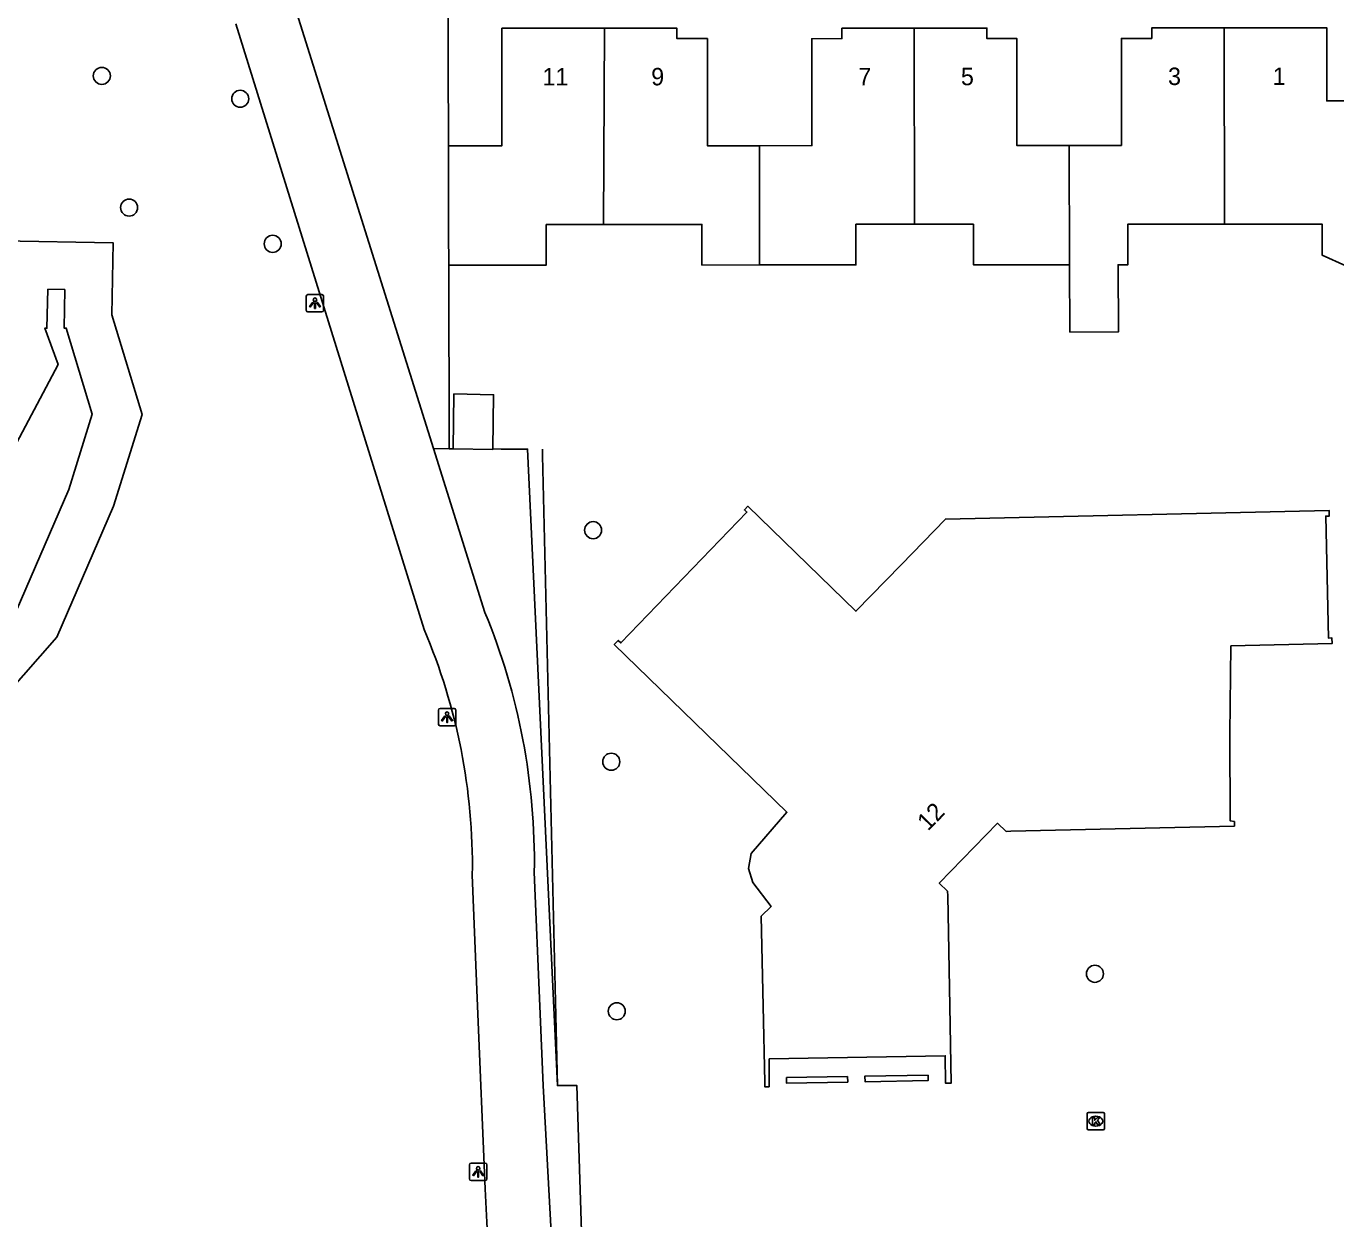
# Model space of a CAD drawing. Extents: x 162880 to 165536, y 384011 to 385179.
# Drawn here: x 163777.7 to 163852.9, y 384237.8 to 384306.2 of the extents above; entities that cross this region are included whole.
import ezdxf

# ---------------------------------------------------------------- set-up
doc = ezdxf.new("R2010")
doc.units = 0
for name, color, linetype in [('IMGEO_Boom', 7, 'Continuous'), ('IMGEO_Fietspad_gesloten', 7, 'Continuous'), ('IMGEO_Groenvoorziening', 7, 'Continuous'), ('IMGEO_Hek', 7, 'Continuous'), ('IMGEO_Kolk', 7, 'Continuous'), ('IMGEO_Lichtpunt', 7, 'Continuous'), ('IMGEO_Pand', 7, 'Continuous'), ('IMGEO_Pand_nummerreeks', 7, 'Continuous'), ('IMGEO_Waterloop', 7, 'Continuous')]:
    doc.layers.add(name, color=color, linetype=linetype)

msp = doc.modelspace()

# ---------------------------------------------------------------- linework, layer by layer
at = {"layer": 'IMGEO_Boom'}
for centre in [(163782.007, 384303.395), (163789.955, 384302.084), (163783.573, 384295.835), (163791.819, 384293.755), (163810.224, 384277.319), (163811.267, 384264.029), (163839.044, 384251.853), (163811.581, 384249.703)]:
    msp.add_circle(centre, 0.489, dxfattribs=at)
at = {"layer": 'IMGEO_Fietspad_gesloten'}
for points in [[(163801.06, 384281.998), (163793.12, 384307.302)], [(163800.515, 384271.617), (163789.704, 384306.385)], [(163801.06, 384281.998), (163804.009, 384272.6)], [(163806.844, 384257.687), (163807.168, 384250), (163807.361, 384245.433), (163808.024, 384233.147)], [(163804.782, 384228.061), (163804.293, 384234.123), (163804.207, 384235.863), (163804.118, 384237.602), (163804.016, 384239.502), (163803.591, 384250), (163803.285, 384257.538)]]:
    msp.add_lwpolyline(points, dxfattribs=at)
for centre, radius, start, end in [((163769.252, 384258.267), 37.597, 359.11675, 22.41053), ((163768.654, 384258.036), 34.635, 359.17548, 23.08573)]:
    msp.add_arc(centre, radius, start, end, dxfattribs=at)
at = {"layer": 'IMGEO_Groenvoorziening'}
for points in [[(163801.871, 384309.184), (163801.92, 384299.385)], [(163776.251, 384293.93), (163782.655, 384293.817), (163782.589, 384289.681), (163784.323, 384283.96), (163782.678, 384278.692), (163779.428, 384271.181), (163766.567, 384256.548)], [(163801.928, 384292.53), (163801.952, 384281.993)], [(163801.952, 384281.993), (163801.06, 384281.998)], [(163801.952, 384281.993), (163802.189, 384281.992)], [(163804.472, 384281.979), (163804.938, 384281.977), (163806.456, 384281.969), (163808.174, 384245.433), (163809.28, 384245.451), (163809.661, 384233.466)]]:
    msp.add_lwpolyline(points, dxfattribs=at)
at = {"layer": 'IMGEO_Hek'}
for points in [[(163807.321, 384281.603), (163807.307, 384281.965)], [(163809.28, 384245.451), (163808.174, 384245.433), (163807.321, 384281.603)]]:
    msp.add_lwpolyline(points, dxfattribs=at)
at = {"layer": 'IMGEO_Kolk'}
for p, q in [((163838.59, 384242.969), (163838.59, 384243.821)), ((163838.665, 384243.895), (163839.517, 384243.895)), ((163839.078, 384243.675), (163839.103, 384243.675)), ((163839.591, 384243.821), (163839.591, 384242.969)), ((163839.517, 384242.895), (163838.665, 384242.895)), ((163839.101, 384243.115), (163839.076, 384243.115))]:
    msp.add_line(p, q, dxfattribs=at)
for points in [[(163838.59, 384242.969), (163838.59, 384243.821)], [(163838.665, 384243.895), (163839.517, 384243.895)], [(163838.911, 384243.595), (163839.034, 384243.595), (163839.034, 384243.444), (163839.164, 384243.595), (163839.328, 384243.595), (163839.182, 384243.444), (163839.335, 384243.195), (163839.183, 384243.195), (163839.098, 384243.359), (163839.034, 384243.292), (163839.034, 384243.195), (163838.911, 384243.195), (163838.911, 384243.595)], [(163839.591, 384243.821), (163839.591, 384242.969)], [(163839.517, 384242.895), (163838.665, 384242.895)]]:
    msp.add_lwpolyline(points, dxfattribs=at)
for centre, start, end in [((163838.667, 384243.819), 91.55205, 178.44795), ((163838.667, 384243.819), 91.55205, 178.44795), ((163839.515, 384243.819), 1.55205, 88.44795), ((163839.515, 384243.819), 1.55205, 88.44795), ((163838.667, 384242.971), 181.55205, 268.44795), ((163838.667, 384242.971), 181.55205, 268.44795), ((163839.515, 384242.971), 271.55205, 358.44795), ((163839.515, 384242.971), 271.55205, 358.44795)]:
    msp.add_arc(centre, 0.0765, start, end, dxfattribs=at)
for centre, major_axis, ratio, start_param, end_param in [((163839.077, 384243.395), (-0.387, 0.002), 0.722429, 4.712389, 7.853982), ((163839.102, 384243.395), (-0.39, 0.002), 0.717154, 1.570796, 4.712389)]:
    msp.add_ellipse(centre, major_axis=major_axis, ratio=ratio, start_param=start_param, end_param=end_param, dxfattribs=at)
at = {"layer": 'IMGEO_Lichtpunt'}
for p, q in [((163793.747, 384290.751), (163793.747, 384289.944)), ((163793.747, 384290.751), (163793.747, 384289.944)), ((163794.649, 384290.846), (163793.841, 384290.846)), ((163794.649, 384290.846), (163793.841, 384290.846)), ((163794.743, 384289.944), (163794.743, 384290.751)), ((163794.743, 384289.944), (163794.743, 384290.751)), ((163793.841, 384289.85), (163794.649, 384289.85)), ((163793.841, 384289.85), (163794.649, 384289.85)), ((163801.337, 384266.991), (163801.337, 384266.184)), ((163801.337, 384266.991), (163801.337, 384266.184)), ((163802.239, 384267.086), (163801.431, 384267.086)), ((163802.239, 384267.086), (163801.431, 384267.086)), ((163802.333, 384266.184), (163802.333, 384266.991)), ((163802.333, 384266.184), (163802.333, 384266.991)), ((163801.431, 384266.09), (163802.239, 384266.09)), ((163801.431, 384266.09), (163802.239, 384266.09)), ((163803.122, 384240.889), (163803.122, 384240.082)), ((163803.122, 384240.889), (163803.122, 384240.082)), ((163804.024, 384240.984), (163803.216, 384240.984)), ((163804.024, 384240.984), (163803.216, 384240.984)), ((163804.118, 384240.082), (163804.118, 384240.889)), ((163804.118, 384240.082), (163804.118, 384240.889)), ((163803.216, 384239.988), (163804.024, 384239.988)), ((163803.216, 384239.988), (163804.024, 384239.988))]:
    msp.add_line(p, q, dxfattribs=at)
for points in [[(163794.121, 384290.415), (163794.16, 384290.387), (163793.972, 384290.125), (163793.934, 384290.152), (163794.121, 384290.415)], [(163794.223, 384290.367), (163794.27, 384290.367), (163794.27, 384290.045), (163794.223, 384290.045), (163794.223, 384290.367)], [(163794.333, 384290.387), (163794.371, 384290.414), (163794.558, 384290.152), (163794.519, 384290.124), (163794.333, 384290.387)], [(163801.711, 384266.655), (163801.75, 384266.627), (163801.562, 384266.365), (163801.524, 384266.392), (163801.711, 384266.655)], [(163801.813, 384266.607), (163801.86, 384266.607), (163801.86, 384266.285), (163801.813, 384266.285), (163801.813, 384266.607)], [(163801.923, 384266.627), (163801.961, 384266.654), (163802.148, 384266.392), (163802.109, 384266.364), (163801.923, 384266.627)], [(163803.496, 384240.553), (163803.535, 384240.525), (163803.347, 384240.263), (163803.309, 384240.29), (163803.496, 384240.553)], [(163803.598, 384240.505), (163803.645, 384240.505), (163803.645, 384240.183), (163803.598, 384240.183), (163803.598, 384240.505)], [(163803.708, 384240.525), (163803.746, 384240.552), (163803.933, 384240.29), (163803.894, 384240.262), (163803.708, 384240.525)]]:
    msp.add_lwpolyline(points, dxfattribs=at)
for centre in [(163794.246, 384290.549), (163801.836, 384266.789), (163803.621, 384240.687)]:
    msp.add_circle(centre, 0.0994, dxfattribs=at)
for centre, start, end in [((163793.841, 384290.751), 90, 180), ((163793.841, 384290.751), 90, 180), ((163794.649, 384290.751), 0, 90), ((163794.649, 384290.751), 0, 90), ((163793.841, 384289.944), 180, 270), ((163793.841, 384289.944), 180, 270), ((163794.649, 384289.944), 270, 0), ((163794.649, 384289.944), 270, 360), ((163801.431, 384266.991), 90, 180), ((163801.431, 384266.991), 90, 180), ((163802.239, 384266.991), 0, 90), ((163802.239, 384266.991), 0, 90), ((163801.431, 384266.184), 180, 270), ((163801.431, 384266.184), 180, 270), ((163802.239, 384266.184), 270, 0), ((163802.239, 384266.184), 270, 360), ((163803.216, 384240.889), 90, 180), ((163803.216, 384240.889), 90, 180), ((163804.024, 384240.889), 0, 90), ((163804.024, 384240.889), 0, 90), ((163803.216, 384240.082), 180, 270), ((163803.216, 384240.082), 180, 270), ((163804.024, 384240.082), 270, 0), ((163804.024, 384240.082), 270, 360)]:
    msp.add_arc(centre, 0.0946, start, end, dxfattribs=at)
at = {"layer": 'IMGEO_Pand'}
for points in [[(163801.92, 384299.385), (163804.986, 384299.387), (163804.981, 384306.126), (163810.869, 384306.13)], [(163810.818, 384294.866), (163810.869, 384306.13)], [(163810.869, 384306.13), (163815.031, 384306.133), (163815.032, 384305.534), (163816.783, 384305.536), (163816.786, 384299.387), (163819.771, 384299.389)], [(163819.771, 384299.389), (163822.786, 384299.391), (163822.783, 384305.531), (163824.513, 384305.533), (163824.513, 384306.133), (163828.668, 384306.136)], [(163828.668, 384306.136), (163832.843, 384306.139), (163832.844, 384305.54), (163834.565, 384305.535), (163834.563, 384299.396), (163837.57, 384299.398)], [(163828.668, 384306.136), (163828.682, 384294.877)], [(163837.57, 384299.398), (163840.563, 384299.4), (163840.568, 384305.548), (163842.309, 384305.551), (163842.308, 384306.15), (163846.47, 384306.152)], [(163846.47, 384306.152), (163852.357, 384306.156), (163852.36, 384301.956), (163854.02, 384301.957), (163856.929, 384300.707)], [(163846.475, 384294.888), (163846.47, 384306.152)], [(163801.92, 384299.385), (163801.926, 384294.386), (163801.928, 384292.53)], [(163819.778, 384292.542), (163819.771, 384299.389)], [(163837.57, 384299.398), (163837.59, 384292.553)], [(163810.818, 384294.866), (163807.527, 384294.864), (163807.528, 384292.534), (163801.928, 384292.53)], [(163819.778, 384292.542), (163816.468, 384292.54), (163816.467, 384294.87), (163810.818, 384294.866)], [(163828.682, 384294.877), (163825.317, 384294.875), (163825.318, 384292.545), (163819.778, 384292.542)], [(163837.59, 384292.553), (163832.068, 384292.55), (163832.067, 384294.88), (163828.682, 384294.877)], [(163846.475, 384294.888), (163840.937, 384294.885), (163840.938, 384292.555), (163840.375, 384292.555), (163840.387, 384288.698), (163837.602, 384288.69), (163837.59, 384292.553)], [(163853.45, 384292.496), (163852.088, 384293.112), (163852.087, 384294.892), (163846.475, 384294.888)], [(163802.189, 384281.992), (163802.227, 384285.144), (163804.509, 384285.094), (163804.472, 384281.979)], [(163802.189, 384281.992), (163802.189, 384281.98), (163804.472, 384281.953), (163804.472, 384281.979)], [(163846.848, 384270.681), (163846.789, 384265.625), (163846.817, 384260.625), (163847.053, 384260.596), (163847.058, 384260.33), (163834.208, 384260.035), (163833.952, 384260.029), (163833.446, 384260.494), (163830.097, 384257.06), (163830.583, 384256.595), (163830.588, 384256.333), (163830.706, 384250), (163830.789, 384245.584), (163830.452, 384245.577), (163830.445, 384247.154), (163820.336, 384246.966), (163820.328, 384245.367), (163820.092, 384245.362), (163820.086, 384245.624), (163819.992, 384250), (163819.88, 384255.158), (163820.441, 384255.716), (163819.399, 384257.099), (163819.147, 384257.895), (163819.296, 384258.761), (163821.357, 384261.126), (163811.439, 384270.756), (163811.664, 384270.992), (163811.822, 384270.849), (163819.059, 384278.354), (163818.911, 384278.486), (163819.109, 384278.69), (163825.312, 384272.663), (163827.906, 384275.332), (163830.457, 384277.957), (163852.492, 384278.449), (163852.5, 384278.13), (163852.3, 384278.126), (163852.456, 384271.127), (163852.656, 384271.131), (163852.663, 384270.811), (163846.848, 384270.681)], [(163824.834, 384245.961), (163824.843, 384245.639), (163821.332, 384245.575), (163821.331, 384245.899), (163824.834, 384245.961)], [(163829.461, 384246.041), (163829.459, 384245.721), (163825.843, 384245.66), (163825.835, 384245.982), (163829.461, 384246.041)]]:
    msp.add_lwpolyline(points, dxfattribs=at)
at = {"layer": 'IMGEO_Waterloop'}
msp.add_lwpolyline([(163751.137, 384246.472), (163756.708, 384251.434), (163764.62, 384258.482), (163777.086, 384272.665), (163780.107, 384279.647), (163781.458, 384283.972), (163779.959, 384288.917), (163779.838, 384288.923), (163779.873, 384291.127), (163778.914, 384291.144), (163778.852, 384288.909), (163778.741, 384288.922), (163779.492, 384286.825), (163776.594, 384281.337), (163774.364, 384274.376), (163753.54, 384252.355), (163751.972, 384251.214), (163744.623, 384245.868)], dxfattribs=at)

# ---------------------------------------------------------------- texts
at = {"layer": 'IMGEO_Pand_nummerreeks'}
for s, rotation, p in [('11', 0.03991, (163807.312, 384302.848)), ('9', 0.03991, (163813.559, 384302.852)), ('7', 0.04127, (163825.455, 384302.854)), ('5', 0.04127, (163831.347, 384302.858)), ('3', 0.03421, (163843.242, 384302.871)), ('1', 0.03421, (163849.251, 384302.874)), ('12', 45.71796, (163829.452, 384260.008))]:
    msp.add_text(s, height=1, rotation=rotation, dxfattribs=at).set_placement(p)

doc.saveas('drawing.dxf')
